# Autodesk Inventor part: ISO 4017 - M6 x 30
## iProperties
Comments: To add or edit properties for Autodesk Inventor files, use iProperties.
Created: 2004-08
Part Number: ISO 4017 - M6 x 30
Vendor: Autodesk Inc.
Document SubType Name: Modeling
Designer: John Blackburn
Material: Default
Description: Hex-Head Bolt
Standard: ISO 4017
Alert: To add or edit properties for Autodesk Inventor files, use iProperties.
Control State: 0
Master: False
Checked Out: False
Shininess: 64.0
Length Units: 11269
Angle Units: 11279
Time Units: 11290
Mass Units: 11283
Length Display Precision: 3
Angle Display Precision: 2
Compacted: True
EGR: 1
Density: 0.0
Volumn: 0.0
Area: 0.0
PropertySet Name: Model Information
Author: John Blackburn
Revision Number: 8
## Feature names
1. Body [Revolution]
2. Head [Extrusion]
3. Chamfer1 [Revolution]
4. Chamfer2
